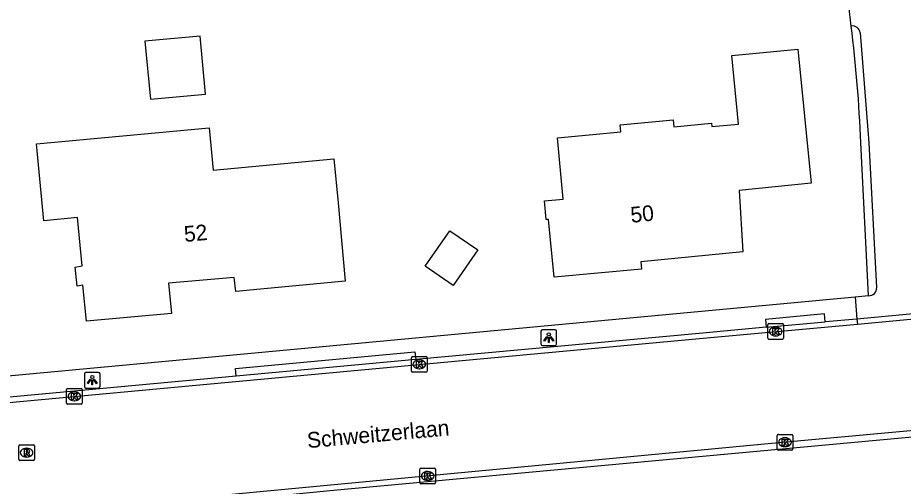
# Model space of a CAD drawing. Extents: x 162157 to 163165, y 378998 to 380775.
# Drawn here: x 162368.4 to 162424.7, y 380633 to 380662.8 of the extents above; entities that cross this region are included whole.
import ezdxf

# ---------------------------------------------------------------- set-up
doc = ezdxf.new("R2010")
doc.units = 0
for name, color, linetype in [('IMGEO_Kolk', 7, 'Continuous'), ('IMGEO_Lichtpunt', 7, 'Continuous'), ('IMGEO_Openbare_ruimte_label', 7, 'Continuous'), ('IMGEO_Pand', 7, 'Continuous'), ('IMGEO_Pand_nummerreeks', 7, 'Continuous'), ('IMGEO_Rijbaan_lokaal_gesloten', 7, 'Continuous'), ('IMGEO_Rijbaan_lokaal_open', 7, 'Continuous'), ('IMGEO_Rioolput', 7, 'Continuous'), ('IMGEO_Voetpad_open', 7, 'Continuous')]:
    doc.layers.add(name, color=color, linetype=linetype)

msp = doc.modelspace()

# ---------------------------------------------------------------- linework, layer by layer
at = {"layer": 'IMGEO_Kolk'}
for p, q in [((162416.063, 380642.407), (162416.063, 380643.259)), ((162416.138, 380643.333), (162416.99, 380643.333)), ((162416.551, 380643.113), (162416.576, 380643.113)), ((162417.064, 380643.259), (162417.064, 380642.407)), ((162416.99, 380642.333), (162416.138, 380642.333)), ((162416.574, 380642.553), (162416.549, 380642.553)), ((162393.416, 380640.316), (162393.416, 380641.168)), ((162393.491, 380641.242), (162394.343, 380641.242)), ((162394.417, 380641.168), (162394.417, 380640.316)), ((162393.904, 380641.022), (162393.929, 380641.022)), ((162394.343, 380640.242), (162393.491, 380640.242)), ((162393.927, 380640.462), (162393.902, 380640.462)), ((162371.493, 380638.285), (162371.493, 380639.137)), ((162371.568, 380639.211), (162372.42, 380639.211)), ((162371.981, 380638.991), (162372.006, 380638.991)), ((162372.494, 380639.137), (162372.494, 380638.285)), ((162372.004, 380638.431), (162371.979, 380638.431)), ((162372.42, 380638.211), (162371.568, 380638.211)), ((162416.661, 380635.373), (162416.661, 380636.225)), ((162416.736, 380636.299), (162417.588, 380636.299)), ((162417.149, 380636.079), (162417.174, 380636.079)), ((162417.662, 380636.225), (162417.662, 380635.373)), ((162417.172, 380635.519), (162417.147, 380635.519)), ((162417.588, 380635.299), (162416.736, 380635.299)), ((162393.95, 380633.232), (162393.95, 380634.084)), ((162394.025, 380634.158), (162394.877, 380634.158)), ((162394.438, 380633.938), (162394.463, 380633.938)), ((162394.951, 380634.084), (162394.951, 380633.232)), ((162394.461, 380633.378), (162394.436, 380633.378)), ((162394.877, 380633.158), (162394.025, 380633.158))]:
    msp.add_line(p, q, dxfattribs=at)
for points in [[(162416.063, 380642.407), (162416.063, 380643.259)], [(162416.138, 380643.333), (162416.99, 380643.333)], [(162416.384, 380643.033), (162416.507, 380643.033), (162416.507, 380642.882), (162416.637, 380643.033), (162416.801, 380643.033), (162416.655, 380642.882), (162416.808, 380642.633), (162416.656, 380642.633), (162416.571, 380642.797), (162416.507, 380642.73), (162416.507, 380642.633), (162416.384, 380642.633), (162416.384, 380643.033)], [(162417.064, 380643.259), (162417.064, 380642.407)], [(162416.99, 380642.333), (162416.138, 380642.333)], [(162393.416, 380640.316), (162393.416, 380641.168)], [(162393.491, 380641.242), (162394.343, 380641.242)], [(162394.417, 380641.168), (162394.417, 380640.316)], [(162393.737, 380640.942), (162393.86, 380640.942), (162393.86, 380640.791), (162393.99, 380640.942), (162394.154, 380640.942), (162394.008, 380640.791), (162394.161, 380640.542), (162394.009, 380640.542), (162393.924, 380640.706), (162393.86, 380640.639), (162393.86, 380640.542), (162393.737, 380640.542), (162393.737, 380640.942)], [(162394.343, 380640.242), (162393.491, 380640.242)], [(162371.493, 380638.285), (162371.493, 380639.137)], [(162371.568, 380639.211), (162372.42, 380639.211)], [(162371.814, 380638.911), (162371.937, 380638.911), (162371.937, 380638.76), (162372.067, 380638.911), (162372.231, 380638.911), (162372.085, 380638.76), (162372.238, 380638.511), (162372.086, 380638.511), (162372.001, 380638.675), (162371.937, 380638.608), (162371.937, 380638.511), (162371.814, 380638.511), (162371.814, 380638.911)], [(162372.494, 380639.137), (162372.494, 380638.285)], [(162372.42, 380638.211), (162371.568, 380638.211)], [(162416.661, 380635.373), (162416.661, 380636.225)], [(162416.736, 380636.299), (162417.588, 380636.299)], [(162417.662, 380636.225), (162417.662, 380635.373)], [(162416.982, 380635.999), (162417.105, 380635.999), (162417.105, 380635.848), (162417.235, 380635.999), (162417.399, 380635.999), (162417.253, 380635.848), (162417.406, 380635.599), (162417.254, 380635.599), (162417.169, 380635.763), (162417.105, 380635.696), (162417.105, 380635.599), (162416.982, 380635.599), (162416.982, 380635.999)], [(162417.588, 380635.299), (162416.736, 380635.299)], [(162393.95, 380633.232), (162393.95, 380634.084)], [(162394.025, 380634.158), (162394.877, 380634.158)], [(162394.271, 380633.858), (162394.394, 380633.858), (162394.394, 380633.707), (162394.524, 380633.858), (162394.688, 380633.858), (162394.542, 380633.707), (162394.695, 380633.458), (162394.543, 380633.458), (162394.458, 380633.622), (162394.394, 380633.555), (162394.394, 380633.458), (162394.271, 380633.458), (162394.271, 380633.858)], [(162394.951, 380634.084), (162394.951, 380633.232)], [(162394.877, 380633.158), (162394.025, 380633.158)]]:
    msp.add_lwpolyline(points, dxfattribs=at)
for centre, start, end in [((162416.14, 380643.257), 91.552, 178.448), ((162416.14, 380643.257), 91.552, 178.448), ((162416.988, 380643.257), 1.552, 88.448), ((162416.988, 380643.257), 1.552, 88.448), ((162416.14, 380642.409), 181.552, 268.448), ((162416.14, 380642.409), 181.552, 268.448), ((162416.988, 380642.409), 271.552, 358.448), ((162416.988, 380642.409), 271.552, 358.448), ((162393.493, 380641.166), 91.552, 178.448), ((162393.493, 380641.166), 91.552, 178.448), ((162394.341, 380641.166), 1.552, 88.448), ((162394.341, 380641.166), 1.552, 88.448), ((162393.493, 380640.318), 181.552, 268.448), ((162393.493, 380640.318), 181.552, 268.448), ((162394.341, 380640.318), 271.552, 358.448), ((162394.341, 380640.318), 271.552, 358.448), ((162371.57, 380639.135), 91.552, 178.448), ((162371.57, 380639.135), 91.552, 178.448), ((162372.418, 380639.135), 1.552, 88.448), ((162372.418, 380639.135), 1.552, 88.448), ((162371.57, 380638.287), 181.552, 268.448), ((162371.57, 380638.287), 181.552, 268.448), ((162372.418, 380638.287), 271.552, 358.448), ((162372.418, 380638.287), 271.552, 358.448), ((162416.738, 380636.223), 91.552, 178.448), ((162416.738, 380636.223), 91.552, 178.448), ((162417.586, 380636.223), 1.552, 88.448), ((162417.586, 380636.223), 1.552, 88.448), ((162416.738, 380635.375), 181.552, 268.448), ((162416.738, 380635.375), 181.552, 268.448), ((162417.586, 380635.375), 271.552, 358.448), ((162417.586, 380635.375), 271.552, 358.448), ((162394.027, 380634.082), 91.552, 178.448), ((162394.027, 380634.082), 91.552, 178.448), ((162394.875, 380634.082), 1.552, 88.448), ((162394.875, 380634.082), 1.552, 88.448), ((162394.027, 380633.234), 181.552, 268.448), ((162394.027, 380633.234), 181.552, 268.448), ((162394.875, 380633.234), 271.552, 358.448), ((162394.875, 380633.234), 271.552, 358.448)]:
    msp.add_arc(centre, 0.0765, start, end, dxfattribs=at)
for centre, major_axis, ratio, start_param, end_param in [((162416.55, 380642.833), (-0.387, 0.002), 0.722429, 4.712389, 7.853982), ((162416.575, 380642.833), (-0.39, 0.002), 0.717154, 1.570796, 4.712389), ((162393.903, 380640.742), (-0.387, 0.002), 0.722429, 4.712389, 7.853982), ((162393.928, 380640.742), (-0.39, 0.002), 0.717154, 1.570796, 4.712389), ((162371.98, 380638.711), (-0.387, 0.002), 0.722429, 4.712389, 7.853982), ((162372.005, 380638.711), (-0.39, 0.002), 0.717154, 1.570796, 4.712389), ((162417.148, 380635.799), (-0.387, 0.002), 0.722429, 4.712389, 7.853982), ((162417.173, 380635.799), (-0.39, 0.002), 0.717154, 1.570796, 4.712389), ((162394.437, 380633.658), (-0.387, 0.002), 0.722429, 4.712389, 7.853982), ((162394.462, 380633.658), (-0.39, 0.002), 0.717154, 1.570796, 4.712389)]:
    msp.add_ellipse(centre, major_axis=major_axis, ratio=ratio, start_param=start_param, end_param=end_param, dxfattribs=at)
at = {"layer": 'IMGEO_Lichtpunt'}
for p, q in [((162401.647, 380642.847), (162401.647, 380642.04)), ((162401.647, 380642.847), (162401.647, 380642.04)), ((162402.549, 380642.942), (162401.741, 380642.942)), ((162402.549, 380642.942), (162401.741, 380642.942)), ((162402.643, 380642.04), (162402.643, 380642.847)), ((162402.643, 380642.04), (162402.643, 380642.847)), ((162401.741, 380641.946), (162402.549, 380641.946)), ((162401.741, 380641.946), (162402.549, 380641.946)), ((162372.634, 380640.141), (162372.634, 380639.334)), ((162372.634, 380640.141), (162372.634, 380639.334)), ((162373.536, 380640.236), (162372.728, 380640.236)), ((162373.536, 380640.236), (162372.728, 380640.236)), ((162373.63, 380639.334), (162373.63, 380640.141)), ((162373.63, 380639.334), (162373.63, 380640.141)), ((162372.728, 380639.24), (162373.536, 380639.24)), ((162372.728, 380639.24), (162373.536, 380639.24))]:
    msp.add_line(p, q, dxfattribs=at)
for points in [[(162402.021, 380642.511), (162402.06, 380642.483), (162401.872, 380642.221), (162401.834, 380642.248), (162402.021, 380642.511)], [(162402.123, 380642.463), (162402.17, 380642.463), (162402.17, 380642.141), (162402.123, 380642.141), (162402.123, 380642.463)], [(162402.233, 380642.483), (162402.271, 380642.51), (162402.458, 380642.248), (162402.419, 380642.22), (162402.233, 380642.483)], [(162373.008, 380639.805), (162373.047, 380639.777), (162372.859, 380639.515), (162372.821, 380639.542), (162373.008, 380639.805)], [(162373.11, 380639.757), (162373.157, 380639.757), (162373.157, 380639.435), (162373.11, 380639.435), (162373.11, 380639.757)], [(162373.22, 380639.777), (162373.258, 380639.804), (162373.445, 380639.542), (162373.406, 380639.514), (162373.22, 380639.777)]]:
    msp.add_lwpolyline(points, dxfattribs=at)
for centre in [(162402.146, 380642.645), (162373.133, 380639.939)]:
    msp.add_circle(centre, 0.0994, dxfattribs=at)
for centre, start, end in [((162401.741, 380642.847), 90, 180), ((162401.741, 380642.847), 90, 180), ((162402.549, 380642.847), 0, 90), ((162402.549, 380642.847), 0, 90), ((162401.741, 380642.04), 180, 270), ((162401.741, 380642.04), 180, 270), ((162402.549, 380642.04), 270, 0), ((162402.549, 380642.04), 270, 360), ((162372.728, 380640.141), 90, 180), ((162372.728, 380640.141), 90, 180), ((162373.536, 380640.141), 0, 90), ((162373.536, 380640.141), 0, 90), ((162372.728, 380639.334), 180, 270), ((162372.728, 380639.334), 180, 270), ((162373.536, 380639.334), 270, 0), ((162373.536, 380639.334), 270, 360)]:
    msp.add_arc(centre, 0.0946, start, end, dxfattribs=at)
at = {"layer": 'IMGEO_Pand'}
for points in [[(162376.484, 380661.264), (162376.827, 380657.587), (162380.326, 380657.914), (162379.983, 380661.591), (162376.484, 380661.264)], [(162406.736, 380655.511), (162406.693, 380655.958), (162410.057, 380656.279), (162410.099, 380655.83), (162412.488, 380656.058), (162412.508, 380655.849), (162414.2, 380656.009), (162413.783, 380660.369), (162417.964, 380660.767), (162418.828, 380652.253), (162414.251, 380651.791), (162414.469, 380647.901), (162407.995, 380647.26), (162408.04, 380646.8), (162402.486, 380646.279), (162402.136, 380649.952), (162401.986, 380649.937), (162401.871, 380651.131), (162403.065, 380651.245), (162402.695, 380655.127), (162406.736, 380655.511)], [(162388.495, 380653.791), (162388.751, 380651.01), (162389.209, 380646.031), (162382.252, 380645.37), (162382.145, 380646.271), (162377.984, 380645.891), (162378.165, 380643.978), (162372.76, 380643.485), (162372.536, 380645.772), (162372.166, 380645.718), (162372.052, 380646.911), (162372.486, 380646.993), (162372.198, 380650.062), (162370.052, 380649.857), (162369.599, 380654.743), (162380.566, 380655.767), (162380.818, 380653.074), (162388.495, 380653.791)], [(162394.297, 380646.974), (162395.857, 380649.235), (162397.634, 380648.008), (162396.074, 380645.747), (162394.297, 380646.974)]]:
    msp.add_lwpolyline(points, dxfattribs=at)
at = {"layer": 'IMGEO_Rijbaan_lokaal_gesloten'}
for points in [[(162421.757, 380643.305), (162430.746, 380644.14), (162434.772, 380644.509), (162462.779, 380646.893)], [(162430.713, 380644.459), (162421.728, 380643.624)], [(162421.728, 380643.624), (162421.757, 380643.305)], [(162334.069, 380635.183), (162337.675, 380635.531), (162411.727, 380642.392), (162421.757, 380643.305)], [(162437.427, 380637.652), (162415.859, 380635.682), (162364.95, 380630.872), (162308.18, 380625.53)], [(162372.405, 380631.16), (162388.242, 380632.742), (162429.631, 380636.541)]]:
    msp.add_lwpolyline(points, dxfattribs=at)
at = {"layer": 'IMGEO_Rijbaan_lokaal_open'}
for points in [[(162421.368, 380662.235), (162421.22, 380663.534)], [(162422.986, 380645.624), (162422.515, 380654.825), (162421.947, 380661.806)], [(162421.612, 380645.024), (162422.469, 380645.107)], [(162421.612, 380645.024), (162421.728, 380643.624)], [(162415.962, 380643.099), (162419.72, 380643.441)], [(162421.728, 380643.624), (162419.72, 380643.441)], [(162415.962, 380643.099), (162411.697, 380642.711), (162393.688, 380641.042)], [(162393.688, 380641.042), (162382.287, 380639.986)], [(162382.287, 380639.986), (162364.212, 380638.311)]]:
    msp.add_lwpolyline(points, dxfattribs=at)
for centre, radius, start, end in [((162421.437, 380661.723), 0.516, 9.2107, 97.7174), ((162422.493, 380645.6), 0.494, 267.2191, 2.7809)]:
    msp.add_arc(centre, radius, start, end, dxfattribs=at)
at = {"layer": 'IMGEO_Rioolput'}
for p, q in [((162368.462, 380634.713), (162368.462, 380635.565)), ((162368.537, 380635.639), (162369.389, 380635.639)), ((162369.463, 380635.565), (162369.463, 380634.713)), ((162368.95, 380635.419), (162368.975, 380635.419)), ((162369.389, 380634.639), (162368.537, 380634.639)), ((162368.973, 380634.859), (162368.948, 380634.859))]:
    msp.add_line(p, q, dxfattribs=at)
for points in [[(162368.462, 380634.713), (162368.462, 380635.565)], [(162368.537, 380635.639), (162369.389, 380635.639)], [(162369.463, 380635.565), (162369.463, 380634.713)], [(162369.051, 380635.337), (162368.799, 380635.339), (162368.799, 380634.939)], [(162368.799, 380634.939), (162368.923, 380634.939), (162368.923, 380635.101), (162368.934, 380635.101)], [(162368.977, 380635.258), (162368.923, 380635.258), (162368.923, 380635.177)], [(162368.923, 380635.177), (162368.975, 380635.177)], [(162368.981, 380635.072), (162369.052, 380634.939), (162369.192, 380634.939), (162369.127, 380635.065)], [(162369.389, 380634.639), (162368.537, 380634.639)]]:
    msp.add_lwpolyline(points, dxfattribs=at)
for centre, radius, start, end in [((162368.539, 380635.563), 0.0765, 91.552, 178.448), ((162368.539, 380635.563), 0.0765, 91.552, 178.448), ((162369.387, 380635.563), 0.0765, 1.552, 88.448), ((162369.387, 380635.563), 0.0765, 1.552, 88.448), ((162368.933, 380635.048), 0.0533, 26.0293, 88.6989), ((162368.959, 380635.366), 0.19, 274.7715, 282.9687), ((162368.983, 380635.162), 0.0964, 77.0061, 93.1865), ((162368.997, 380635.219), 0.0378, 276.6634, 79.6772), ((162369.05, 380635.227), 0.109, 350.3612, 89.416), ((162369.048, 380635.227), 0.112, 277.5842, 350.9817), ((162369.032, 380635.012), 0.108, 29.5134, 73.7905), ((162368.539, 380634.715), 0.0765, 181.552, 268.448), ((162368.539, 380634.715), 0.0765, 181.552, 268.448), ((162369.387, 380634.715), 0.0765, 271.552, 358.448), ((162369.387, 380634.715), 0.0765, 271.552, 358.448)]:
    msp.add_arc(centre, radius, start, end, dxfattribs=at)
for centre, major_axis, ratio, start_param, end_param in [((162368.949, 380635.139), (-0.387, 0.002), 0.722429, 4.712389, 7.853982), ((162368.974, 380635.139), (-0.39, 0.002), 0.717154, 1.570796, 4.712389)]:
    msp.add_ellipse(centre, major_axis=major_axis, ratio=ratio, start_param=start_param, end_param=end_param, dxfattribs=at)
at = {"layer": 'IMGEO_Voetpad_open'}
for points in [[(162422.469, 380645.107), (162421.979, 380654.811)], [(162333.922, 380636.869), (162421.612, 380645.024)], [(162419.72, 380643.441), (162419.674, 380643.945), (162415.917, 380643.6), (162415.962, 380643.099)], [(162382.287, 380639.986), (162382.241, 380640.483), (162393.642, 380641.539), (162393.688, 380641.042)]]:
    msp.add_lwpolyline(points, dxfattribs=at)
msp.add_arc((162329.221, 380650.914), 92.84, 2.40566, 7.00409, dxfattribs=at)

# ---------------------------------------------------------------- texts
at = {"layer": 'IMGEO_Openbare_ruimte_label'}
msp.add_text('Schweitzerlaan', height=1, rotation=5.1633, dxfattribs=at).set_placement((162386.832, 380635.418))
at = {"layer": 'IMGEO_Pand_nummerreeks'}
for s, rotation, p in [('50', 5.6545, (162407.389, 380649.733)), ('52', 5.218, (162379.01, 380648.515))]:
    msp.add_text(s, height=1, rotation=rotation, dxfattribs=at).set_placement(p)

doc.saveas('drawing.dxf')
